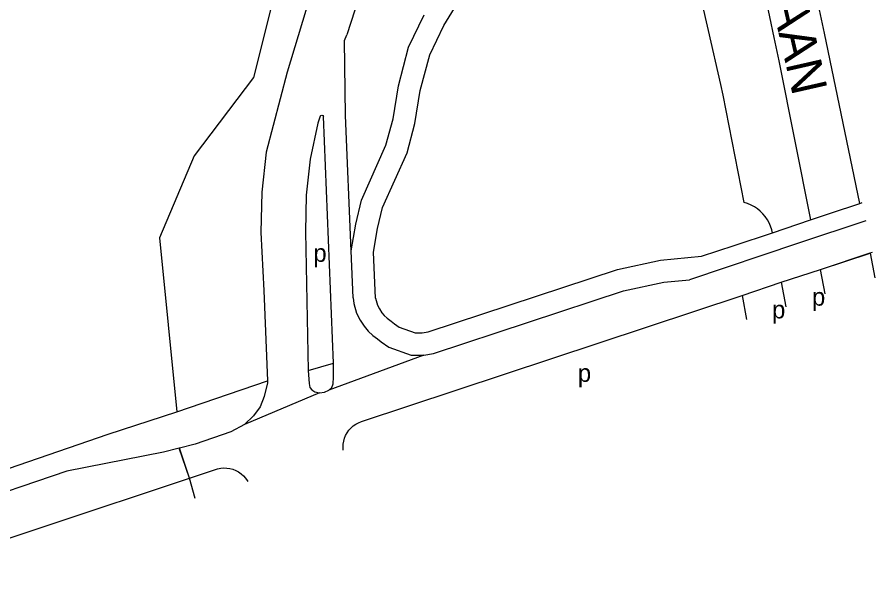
# Model space of a CAD drawing. Extents: x 159441 to 162086, y 388175 to 389787.
# Drawn here: x 161893.2 to 162085.8, y 388405.5 to 388530.4 of the extents above; entities that cross this region are included whole.
import ezdxf

# ---------------------------------------------------------------- set-up
doc = ezdxf.new("R2010")
doc.units = 0
for name, color, linetype in [('BLT_Basislijn', 7, 'Continuous'), ('BLT_Centroide', 7, 'Continuous'), ('BLT_Straatnaam_hoofdweg', 7, 'Continuous'), ('BLT_Vlakafsluiter', 7, 'Continuous')]:
    doc.layers.add(name, color=color, linetype=linetype)

msp = doc.modelspace()

# ---------------------------------------------------------------- linework, layer by layer
at = {"layer": 'BLT_Basislijn'}
for p, q in [((161964.26, 388452.69), (161961.97, 388508.12)), ((161968.22, 388477.9), (161966.97, 388508.33)), ((161968.66, 388467.32), (161968.22, 388477.9)), ((161973.66, 388467.28), (161973.24, 388477.58)), ((161958.56, 388451), (161964.26, 388452.69)), ((161929.09, 388441.73), (161949.4, 388448.7)), ((161929.64, 388433.55), (161929.68, 388433.57))]:
    msp.add_line(p, q, dxfattribs=at)
for points in [[(161904.46, 388741.36), (161923.41, 388674.18), (161940.12, 388631.33), (161951.55, 388596.28), (161955.57, 388570.39), (161953.68, 388546.52), (161946.27, 388516.87), (161932.96, 388499.28), (161925.17, 388480.81), (161929.09, 388441.73)], [(161970.07, 388609.03), (161970.88, 388604.75), (161972.24, 388595.39), (161973.23, 388585.46), (161973.65, 388575.7), (161973.58, 388565.79), (161973.12, 388555.23), (161971.34, 388541.56), (161969.04, 388531.99), (161967.21, 388526.47)], [(161959.77, 388601.99), (161962.45, 388577.5), (161963.15, 388556.09), (161961.49, 388543.38), (161953.88, 388518.08), (161949.11, 388500.1), (161948.14, 388491.08), (161947.96, 388482.03), (161948.63, 388469), (161949.4, 388448.7)], [(162056.43, 388488.76), (162051.71, 388512.9), (162051.19, 388515.26), (162048.46, 388527.4), (162045.66, 388539.53)], [(162060.18, 388539.88), (162063.12, 388525.87), (162064.21, 388520.57), (162071.34, 388484.84)], [(162082.41, 388488.56), (162074.5, 388526.81), (162072.43, 388536.3)], [(161973.24, 388477.58), (161974.15, 388482.91), (161975.28, 388487.64), (161980.75, 388499.94), (161982.54, 388506.51), (161983.72, 388513.95), (161985.84, 388521.95), (161989.01, 388528.51), (161993.22, 388535.43)], [(161968.22, 388477.9), (161969.24, 388483.92), (161970.52, 388489.25), (161976.03, 388501.63), (161977.65, 388507.56), (161978.82, 388514.98), (161981.12, 388523.7), (161984.62, 388530.9)], [(161966.97, 388508.33), (161966.71, 388525.17), (161967.21, 388526.47)], [(161961.25, 388508.15), (161960.76, 388506.55), (161958.99, 388498.49), (161958.13, 388490.44), (161957.96, 388482.18), (161958.56, 388451)], [(161961.25, 388508.15), (161961.4, 388508.31), (161961.62, 388508.4), (161961.83, 388508.32), (161961.97, 388508.12)], [(162062.76, 388481.95), (162062.61, 388482.62), (162062.36, 388483.41), (162062.03, 388484.17), (162061.64, 388484.9), (162061.17, 388485.59), (162060.64, 388486.23), (162060.05, 388486.81), (162059.41, 388487.34), (162058.72, 388487.8), (162057.99, 388488.19), (162057.22, 388488.52), (162056.43, 388488.76)], [(162071.34, 388484.84), (162075.8, 388486.34), (162082.41, 388488.56)], [(162082.41, 388488.56), (162082.92, 388488.74)], [(162083.78, 388484.62), (162068.6, 388479.62), (162044.13, 388471.4)], [(162062.76, 388481.95), (162071.34, 388484.84)], [(162046.82, 388476.71), (162054.21, 388479.07), (162062.76, 388481.95)], [(161973.66, 388467.28), (161974.12, 388465.71), (161974.54, 388464.85), (161975.1, 388464), (161975.66, 388463.35), (161976.32, 388462.73), (161977.17, 388462.08), (161977.93, 388461.49), (161978.99, 388460.75), (161982.55, 388459.49), (161984.13, 388459.48), (161985.47, 388459.71), (162028.03, 388473.74), (162037.64, 388475.77), (162046.82, 388476.71)], [(162073.56, 388473.74), (162084.71, 388477.44)], [(162084.71, 388477.44), (162085.24, 388477.62)], [(162084.71, 388477.44), (162084.72, 388477.39)], [(162084.72, 388477.39), (162085.77, 388471.83)], [(162064.77, 388470.82), (162073.56, 388473.74)], [(162073.57, 388473.69), (162073.56, 388473.74)], [(162074.6, 388468.2), (162073.57, 388473.69)], [(161984.55, 388454.48), (161986.69, 388454.85), (162029.34, 388468.91), (162038.41, 388470.82), (162044.13, 388471.4)], [(162055.95, 388467.89), (162064.77, 388470.82)], [(162064.77, 388470.82), (162065.81, 388465.34)], [(161966.45, 388433.07), (161966.4, 388433.73), (161966.43, 388434.42), (161966.54, 388435.11), (161966.72, 388435.77), (161966.98, 388436.41), (161967.32, 388437.02), (161967.72, 388437.58), (161968.18, 388438.09), (161968.7, 388438.55), (161969.27, 388438.94), (161969.88, 388439.26), (161970.52, 388439.52), (162055.95, 388467.89)], [(161968.66, 388467.32), (161968.81, 388466.05), (161969.44, 388463.89), (161970.2, 388462.35), (161971.1, 388460.99), (161972.05, 388459.87), (161973.1, 388458.9), (161974.1, 388458.14), (161974.95, 388457.47), (161976.69, 388456.26), (161981.68, 388454.49), (161984.55, 388454.48)], [(162055.95, 388467.89), (162056.98, 388462.48)], [(161958.56, 388451), (161958.75, 388448.06), (161958.95, 388447.22), (161959.39, 388446.67), (161960.07, 388446.19), (161961.09, 388445.97)], [(161963.2, 388446.59), (161963.91, 388447.22), (161964.21, 388448.01), (161964.26, 388449.53), (161964.26, 388452.69)], [(161949.4, 388448.7), (161949.42, 388448.2), (161948.66, 388445.16), (161947.75, 388442.84), (161946.31, 388440.82), (161944.24, 388438.86)], [(161961.09, 388445.97), (161962.24, 388446.11), (161963.2, 388446.59)], [(161855.52, 388421.49), (161855.89, 388421.55), (161865.42, 388422.76), (161884.98, 388427), (161889.02, 388428.21), (161913.63, 388436.68), (161929.09, 388441.73)], [(161944.24, 388438.86), (161941.17, 388437.26)], [(161941.17, 388437.26), (161933.2, 388434.47), (161929.68, 388433.57)], [(161929.64, 388433.55), (161926.07, 388432.64), (161904.36, 388428.35), (161856.88, 388412.18), (161855.18, 388411.45)], [(161931.96, 388426.82), (161938.24, 388428.91), (161938.93, 388429.04), (161939.62, 388429.1), (161940.32, 388429.08), (161941, 388428.98), (161941.68, 388428.8), (161942.32, 388428.54), (161942.93, 388428.21), (161943.51, 388427.81), (161944.03, 388427.35), (161944.49, 388426.84), (161944.9, 388426.27), (161944.99, 388426.1)], [(161867.98, 388405.53), (161931.92, 388426.8)], [(161931.92, 388426.8), (161931.96, 388426.82)], [(161933.16, 388422.26), (161931.92, 388426.8)]]:
    msp.add_lwpolyline(points, dxfattribs=at)
at = {"layer": 'BLT_Vlakafsluiter'}
for p, q in [((162073.57, 388473.69), (162084.72, 388477.39)), ((161984.55, 388454.48), (161963.2, 388446.59)), ((161961.09, 388445.97), (161944.24, 388438.86)), ((161931.92, 388426.8), (161929.64, 388433.55)), ((161931.96, 388426.82), (161929.68, 388433.57))]:
    msp.add_line(p, q, dxfattribs=at)

# ---------------------------------------------------------------- texts
at = {"layer": 'BLT_Centroide'}
for p in [(161959.74, 388475.42), (162071.66, 388465.57), (162062.7, 388462.71), (162019.1, 388448.45)]:
    msp.add_text('p', height=4, dxfattribs=at).set_placement(p)
at = {"layer": 'BLT_Straatnaam_hoofdweg'}
msp.add_text('JOHN F KENNEDYLAAN', height=8, rotation=282.8552, dxfattribs=at).set_placement((162040.43, 388630.69))

doc.saveas('drawing.dxf')
